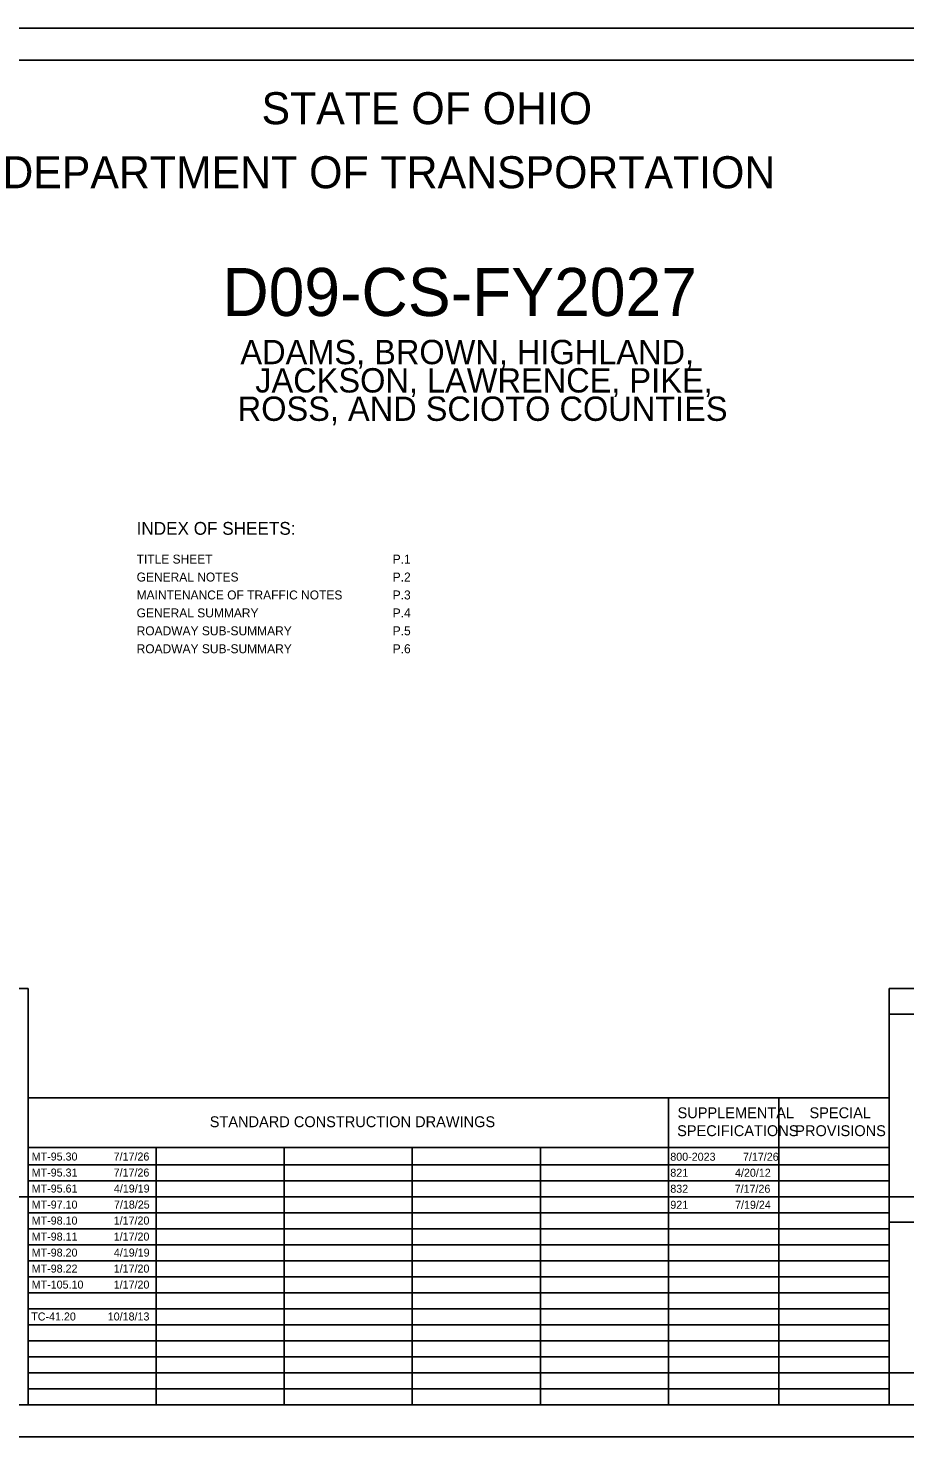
# Model space of a CAD drawing. Extents: x 0 to 40.2, y 0 to 22.
# Drawn here: x 10.15 to 23.84, y 0 to 22 of the extents above; entities that cross this region are included whole.
import ezdxf

# ---------------------------------------------------------------- set-up
doc = ezdxf.new("R2010")
doc.units = 0
for name, color, linetype in [('Default', 7, 'Continuous'), ('SH_Border', 7, 'Continuous'), ('SH_Cut_Line', 7, 'Continuous'), ('SH_Data', 7, 'Continuous'), ('SH_Text', 7, 'Continuous')]:
    doc.layers.add(name, color=color, linetype=linetype)

msp = doc.modelspace()

# ---------------------------------------------------------------- linework, layer by layer
at = {"layer": 'SH_Border'}
msp.add_lwpolyline([(1.5, 21.5), (33.5, 21.5), (33.5, 0.5), (1.5, 0.5)], close=True, dxfattribs=at)
at = {"layer": 'SH_Cut_Line'}
msp.add_lwpolyline([(0, 0), (34, 0), (34, 22), (0, 22)], close=True, dxfattribs=at)
at = {"layer": 'SH_Data'}
for p, q in [((23.6, 6.6), (26.4, 6.6)), ((10.15, 5.292), (23.6, 5.292)), ((10.15, 0.5), (10.15, 5.292)), ((20.15, 0.5), (20.15, 5.292)), ((21.875, 0.5), (21.875, 5.292)), ((23.6, 0.5), (23.6, 5.292)), ((10.15, 4.521), (23.6, 4.521)), ((12.15, 0.5), (12.15, 4.521)), ((14.15, 0.5), (14.15, 4.521)), ((16.15, 0.5), (16.15, 4.521)), ((18.15, 0.5), (18.15, 4.521)), ((10.15, 4.25), (23.6, 4.25)), ((10.15, 4), (23.6, 4)), ((10.15, 3.75), (23.6, 3.75)), ((23.6, 0.5), (23.6, 3.75)), ((23.6, 3.75), (26.4, 3.75)), ((10.15, 3.5), (23.6, 3.5)), ((23.6, 3.35), (26.4, 3.35)), ((23.6, 3.35), (26.4, 3.35)), ((10.15, 3.25), (23.6, 3.25)), ((10.15, 3), (23.6, 3)), ((10.15, 2.75), (23.6, 2.75)), ((10.15, 2.5), (23.6, 2.5)), ((10.15, 2.25), (23.6, 2.25)), ((10.15, 2), (23.6, 2)), ((10.15, 1.75), (23.6, 1.75)), ((10.15, 1.5), (23.6, 1.5)), ((10.15, 1.25), (23.6, 1.25)), ((10.15, 1), (23.6, 1)), ((10.15, 0.75), (23.6, 0.75)), ((23.6, 0.5), (26.4, 0.5))]:
    msp.add_line(p, q, dxfattribs=at)
for points in [[(10.15, 7), (7.35, 7), (7.35, 3.75), (10.15, 3.75)], [(26.4, 7), (23.6, 7), (23.6, 3.75), (26.4, 3.75)], [(10.15, 3.75), (7.35, 3.75), (7.35, 0.5), (10.15, 0.5)], [(26.4, 3.75), (23.6, 3.75), (23.6, 0.5), (26.4, 0.5)], [(23.6, 0.5), (23.6, 1), (26.4, 1), (26.4, 0.5)]]:
    msp.add_lwpolyline(points, close=True, dxfattribs=at)

# ---------------------------------------------------------------- texts
at = {"layer": 'Default'}
for s, p in [('MT-95.30', (10.205, 4.315)), ('7/17/26', (11.485, 4.315)), ('800-2023', (20.18, 4.312)), ('7/17/26', (21.315, 4.312)), ('MT-95.31', (10.205, 4.065)), ('7/17/26', (11.485, 4.065)), ('821', (20.18, 4.062)), ('4/20/12', (21.191, 4.062)), ('MT-95.61', (10.205, 3.815)), ('4/19/19', (11.489, 3.815)), ('832', (20.18, 3.812)), ('7/17/26', (21.185, 3.812)), ('MT-97.10', (10.205, 3.565)), ('7/18/25', (11.49, 3.565)), ('921', (20.18, 3.562)), ('7/19/24', (21.192, 3.562)), ('MT-98.10', (10.205, 3.315)), ('1/17/20', (11.486, 3.315)), ('MT-98.11', (10.205, 3.065)), ('1/17/20', (11.486, 3.065)), ('MT-98.20', (10.205, 2.815)), ('4/19/19', (11.489, 2.815)), ('MT-98.22', (10.205, 2.565)), ('1/17/20', (11.486, 2.565)), ('MT-105.10', (10.205, 2.315)), ('1/17/20', (11.486, 2.315)), ('TC-41.20', (10.198, 1.817)), ('10/18/13', (11.393, 1.817))]:
    msp.add_text(s, height=0.125, dxfattribs=at).set_placement(p)
at = {"layer": 'SH_Text'}
for s, height, p in [('STATE OF OHIO', 0.5, (13.795, 20.5)), ('DEPARTMENT OF TRANSPORTATION', 0.5, (9.747, 19.5)), ('D09-CS-FY2027', 0.75, (13.182, 17.505)), ('ADAMS, BROWN, HIGHLAND,', 0.38, (13.465, 16.752)), ('JACKSON, LAWRENCE, PIKE,', 0.38, (13.697, 16.31)), ('ROSS, AND SCIOTO COUNTIES', 0.38, (13.423, 15.867)), ('INDEX OF SHEETS:', 0.2, (11.844, 14.088)), ('TITLE SHEET', 0.14, (11.844, 13.638)), ('P.1', 0.14, (15.844, 13.638)), ('GENERAL NOTES', 0.14, (11.844, 13.358)), ('P.2', 0.14, (15.844, 13.358)), ('MAINTENANCE OF TRAFFIC NOTES', 0.14, (11.844, 13.078)), ('P.3', 0.14, (15.844, 13.078)), ('GENERAL SUMMARY', 0.14, (11.844, 12.798)), ('P.4', 0.14, (15.844, 12.798)), ('ROADWAY SUB-SUMMARY', 0.14, (11.844, 12.518)), ('P.5', 0.14, (15.844, 12.518)), ('ROADWAY SUB-SUMMARY', 0.14, (11.844, 12.238)), ('P.6', 0.14, (15.844, 12.238)), ('SUPPLEMENTAL', 0.17, (20.293, 4.976)), ('SPECIAL', 0.17, (22.354, 4.976)), ('STANDARD CONSTRUCTION DRAWINGS', 0.17, (12.986, 4.836)), ('SPECIFICATIONS', 0.17, (20.287, 4.696)), ('PROVISIONS', 0.17, (22.132, 4.696))]:
    msp.add_text(s, height=height, dxfattribs=at).set_placement(p)

doc.saveas('drawing.dxf')
